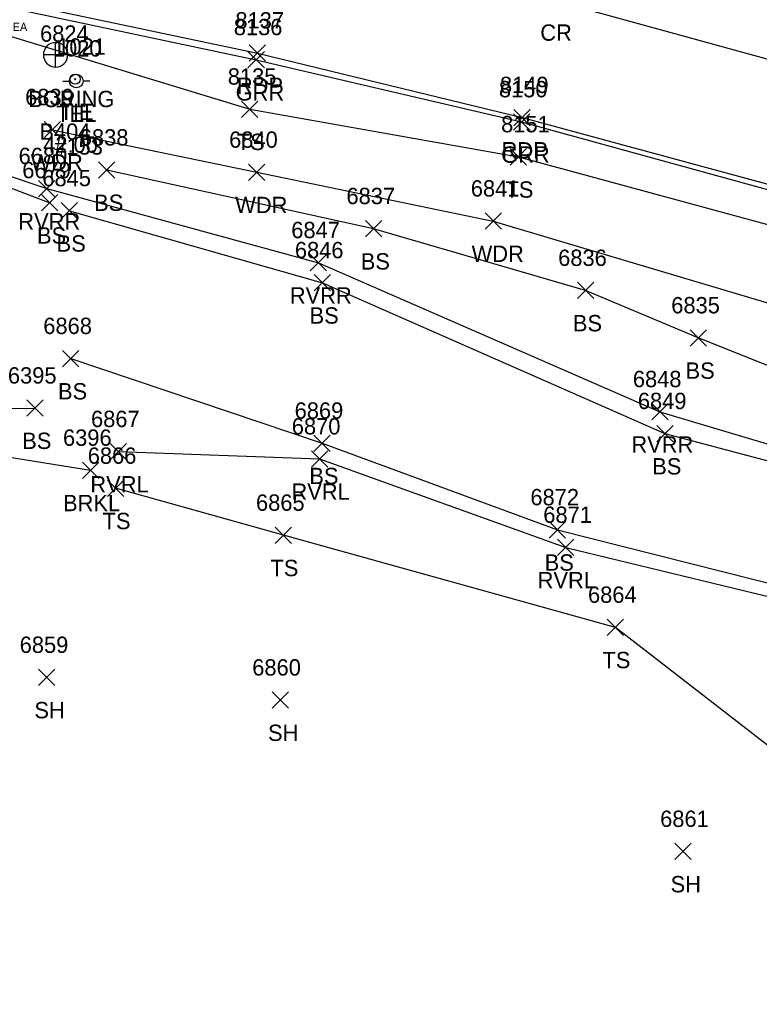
# Model space of a CAD drawing. Extents: x 1588028 to 1589597, y 137576 to 138176.
# Drawn here: x 1588986.3 to 1589076.8, y 137712.9 to 137833.8 of the extents above; entities that cross this region are included whole.
import ezdxf

# ---------------------------------------------------------------- set-up
doc = ezdxf.new("R2010")
doc.units = 0
for name, color, linetype in [('B_C', 7, 'Continuous'), ('C_A', 7, 'Continuous'), ('C_C', 7, 'Continuous'), ('C_I', 7, 'Continuous'), ('CBP', 7, 'Continuous'), ('G_A', 7, 'Continuous'), ('G_C', 7, 'Continuous'), ('G_I', 7, 'Continuous'), ('GA_P', 7, 'Continuous'), ('L_A', 7, 'Continuous'), ('L_I', 7, 'Continuous'), ('L_TIC', 7, 'Continuous'), ('LAWA', 7, 'Continuous'), ('LAWE', 7, 'Continuous'), ('LELB', 7, 'Continuous'), ('P_A', 7, 'Continuous'), ('P_I', 7, 'Continuous'), ('P_TIC', 7, 'Continuous'), ('PET', 7, 'Continuous'), ('PRC', 7, 'Continuous'), ('R_A', 7, 'Continuous'), ('R_I', 7, 'Continuous'), ('R_TIC', 7, 'Continuous'), ('RGR', 7, 'Continuous'), ('U_A', 7, 'Continuous'), ('U_C', 7, 'Continuous'), ('U_I', 7, 'Continuous'), ('UP', 7, 'Continuous')]:
    doc.layers.add(name, color=color, linetype=linetype)

msp = doc.modelspace()

# ---------------------------------------------------------------- linework, layer by layer
at = {"layer": 'CBP'}
for radius in [0.625, 0.0833]:
    msp.add_circle((1588993.08, 137826.57), radius, dxfattribs=at)
at = {"layer": 'GA_P'}
for p, q in [((1588990.69, 137829.55), (1588990.69, 137831.05)), ((1588990.69, 137829.55), (1588989.19, 137829.55)), ((1588992.19, 137829.55), (1588990.69, 137829.55)), ((1588990.69, 137828.05), (1588990.69, 137829.55))]:
    msp.add_line(p, q, dxfattribs=at)
for start, end in [(90, 180), (0, 90), (180, 270), (270, 0)]:
    msp.add_arc((1588990.69, 137829.55), 1.5, start, end, dxfattribs=at)
at = {"layer": 'L_TIC'}
for points in [[(1589013.45, 137821.9), (1589015.45, 137823.9)], [(1589015.45, 137821.9), (1589013.45, 137823.9)], [(1588989.27, 137819.39), (1588991.27, 137821.39)], [(1588991.27, 137819.39), (1588989.27, 137821.39)], [(1589046.33, 137816.07), (1589048.33, 137818.07)], [(1589048.33, 137816.07), (1589046.33, 137818.07)], [(1588995.95, 137814.45), (1588997.95, 137816.45)], [(1588997.95, 137814.45), (1588995.95, 137816.45)], [(1589014.31, 137814.18), (1589016.31, 137816.18)], [(1589016.31, 137814.18), (1589014.31, 137816.18)], [(1588988.6, 137812.18), (1588990.6, 137814.18)], [(1588990.6, 137812.18), (1588988.6, 137814.18)], [(1588988.97, 137810.45), (1588990.97, 137812.45)], [(1588990.97, 137810.45), (1588988.97, 137812.45)], [(1588991.37, 137809.47), (1588993.37, 137811.47)], [(1588993.37, 137809.47), (1588991.37, 137811.47)], [(1589043.24, 137808.21), (1589045.24, 137810.21)], [(1589045.24, 137808.21), (1589043.24, 137810.21)], [(1589028.59, 137807.28), (1589030.59, 137809.28)], [(1589030.59, 137807.28), (1589028.59, 137809.28)], [(1589021.84, 137803.12), (1589023.84, 137805.12)], [(1589023.84, 137803.12), (1589021.84, 137805.12)], [(1589022.33, 137800.66), (1589024.33, 137802.66)], [(1589024.33, 137800.66), (1589022.33, 137802.66)], [(1589054.55, 137799.72), (1589056.55, 137801.72)], [(1589056.55, 137799.72), (1589054.55, 137801.72)], [(1589068.34, 137793.92), (1589070.34, 137795.92)], [(1589070.34, 137793.92), (1589068.34, 137795.92)], [(1588991.54, 137791.39), (1588993.54, 137793.39)], [(1588993.54, 137791.39), (1588991.54, 137793.39)], [(1588987.16, 137785.33), (1588989.16, 137787.33)], [(1588989.16, 137785.33), (1588987.16, 137787.33)], [(1589063.64, 137784.89), (1589065.64, 137786.89)], [(1589065.64, 137784.89), (1589063.64, 137786.89)], [(1589064.26, 137782.21), (1589066.26, 137784.21)], [(1589066.26, 137782.21), (1589064.26, 137784.21)], [(1588997.37, 137780.01), (1588999.37, 137782.01)], [(1588999.37, 137780.01), (1588997.37, 137782.01)], [(1589022.3, 137781.03), (1589024.3, 137783.03)], [(1589024.3, 137781.03), (1589022.3, 137783.03)], [(1589021.99, 137779.11), (1589023.99, 137781.11)], [(1589023.99, 137779.11), (1589021.99, 137781.11)], [(1588993.96, 137777.72), (1588995.96, 137779.72)], [(1588995.96, 137777.72), (1588993.96, 137779.72)], [(1588997.03, 137775.52), (1588999.03, 137777.52)], [(1588999.03, 137775.52), (1588997.03, 137777.52)], [(1589051.1, 137770.44), (1589053.1, 137772.44)], [(1589053.1, 137770.44), (1589051.1, 137772.44)], [(1589017.57, 137769.77), (1589019.57, 137771.77)], [(1589019.57, 137769.77), (1589017.57, 137771.77)], [(1589052.11, 137768.29), (1589054.11, 137770.29)], [(1589054.11, 137768.29), (1589052.11, 137770.29)], [(1589058.2, 137758.51), (1589060.2, 137760.51)], [(1589060.2, 137758.51), (1589058.2, 137760.51)], [(1588988.61, 137752.38), (1588990.61, 137754.38)], [(1588990.61, 137752.38), (1588988.61, 137754.38)], [(1589017.19, 137749.61), (1589019.19, 137751.61)], [(1589019.19, 137749.61), (1589017.19, 137751.61)], [(1589066.46, 137731.09), (1589068.46, 137733.09)], [(1589068.46, 137731.09), (1589066.46, 137733.09)]]:
    msp.add_lwpolyline(points, dxfattribs=at)
at = {"layer": 'LAWA'}
msp.add_lwpolyline([(1588990.27, 137820.39), (1589015.31, 137815.18), (1589044.24, 137809.21), (1589082.76, 137797.73), (1589102.27, 137783.77), (1589136.15, 137768.8), (1589160.7, 137757.03)], dxfattribs=at)
at = {"layer": 'LAWE'}
for points in [[(1588965.44, 137832.87), (1588973.43, 137818.62), (1588989.6, 137813.18), (1589022.84, 137804.12), (1589064.64, 137785.89), (1589085.42, 137779.69), (1589097.72, 137781.17), (1589112.63, 137775.03), (1589131.45, 137759.72), (1589147.93, 137745.25), (1589161.35, 137734.82)], [(1588713.41, 137823.71), (1588738.42, 137825.5), (1588767.27, 137826.98), (1588799.24, 137826.53), (1588827.86, 137827.03), (1588853.9, 137816.5), (1588892.67, 137800.6), (1588920.93, 137790.22), (1588953.81, 137785.34), (1588994.96, 137778.72)], [(1588998.37, 137781.01), (1589022.99, 137780.11), (1589053.11, 137769.29), (1589085.17, 137761.52), (1589118.32, 137748.59), (1589139.23, 137719.4), (1589162.49, 137704.02), (1589194.14, 137678.84), (1589218.55, 137662.87), (1589237.06, 137655.88), (1589274.24, 137640.2), (1589299.98, 137630.61), (1589325.3, 137627.35), (1589364.55, 137614.89), (1589400.15, 137603.63), (1589430.64, 137600.05), (1589464.28, 137596.09), (1589486.71, 137581.4)]]:
    msp.add_lwpolyline(points, dxfattribs=at)
at = {"layer": 'LELB'}
for points in [[(1588976.95, 137800.76), (1588950.62, 137796.9), (1588914.44, 137812.1), (1588887.83, 137826.14), (1588862.59, 137838.68), (1588839.41, 137844.48), (1588814.28, 137844.58), (1588790.42, 137844.54), (1588761.5, 137843.62), (1588744.06, 137845.91), (1588711.1, 137839.15), (1588710.72, 137829.12), (1588738.02, 137826.67), (1588767.07, 137829.2), (1588800.85, 137829.84), (1588826.76, 137827.94), (1588856.44, 137818.62), (1588893.47, 137804.61), (1588923.15, 137792.66), (1588953.98, 137786.08), (1588988.16, 137786.33)], [(1588964.15, 137832.41), (1588972.64, 137818.05), (1588989.97, 137811.45)], [(1588982.15, 137832.74), (1589014.45, 137822.9), (1589047.33, 137817.07), (1589086.55, 137806.43), (1589114.04, 137794.2), (1589138.04, 137783.39), (1589164.04, 137781.22)], [(1589092.95, 137785.5), (1589069.34, 137794.92), (1589055.55, 137800.72), (1589029.59, 137808.28), (1588996.95, 137815.45)], [(1588992.37, 137810.47), (1589023.33, 137801.66), (1589065.26, 137783.21), (1589085.4, 137777.87), (1589097.27, 137780.08), (1589112.23, 137773.55), (1589130.4, 137758.11), (1589147.06, 137743.95), (1589161.02, 137733.26), (1589186.97, 137714.57), (1589213.06, 137701.82), (1589227.47, 137691.94), (1589245.18, 137673.31), (1589268.48, 137660.8), (1589296.93, 137655.07), (1589325.66, 137650.73)], [(1588992.54, 137792.39), (1589023.3, 137782.03), (1589052.1, 137771.44), (1589084.42, 137763.28), (1589121.54, 137752.14), (1589143.04, 137720.61), (1589163.05, 137704.95), (1589194.58, 137680.14), (1589220, 137665.12), (1589237.76, 137657.31), (1589273.63, 137642.37), (1589300.04, 137631.76), (1589324.52, 137628.67), (1589366.23, 137617.74), (1589400.05, 137606.05), (1589430.12, 137603.56), (1589464.26, 137598.64), (1589483.45, 137589.04)], [(1589107.98, 137721.88), (1589082.2, 137741.69), (1589059.2, 137759.51), (1589018.57, 137770.77), (1588998.03, 137776.52)]]:
    msp.add_lwpolyline(points, dxfattribs=at)
at = {"layer": 'P_TIC'}
for points in [[(1589014.38, 137828.77), (1589016.38, 137830.77)], [(1589016.38, 137828.77), (1589014.38, 137830.77)], [(1589046.77, 137820.87), (1589048.77, 137822.87)], [(1589048.77, 137820.87), (1589046.77, 137822.87)]]:
    msp.add_lwpolyline(points, dxfattribs=at)
at = {"layer": 'PET'}
msp.add_lwpolyline([(1588976.42, 137837.98), (1589015.38, 137829.77), (1589047.77, 137821.87), (1589087.62, 137811.07), (1589117.34, 137801.67), (1589165.82, 137785.25), (1589185.23, 137778.17), (1589232.28, 137760.8), (1589265.32, 137747.81), (1589310.31, 137729.83), (1589359.63, 137709.23), (1589389.55, 137696.8), (1589422.31, 137682.69), (1589446.91, 137672.54)], dxfattribs=at)
at = {"layer": 'PRC'}
msp.add_lwpolyline([(1588964.71, 137855.4), (1588980.14, 137852.51), (1589018.19, 137844.35), (1589051.57, 137836.27), (1589092.27, 137825.07), (1589122.68, 137816.23), (1589170.7, 137800.29), (1589190.72, 137793.38), (1589238.44, 137775.62), (1589271.31, 137762.4), (1589315.94, 137744.35), (1589366.22, 137723.58), (1589395.71, 137710.87), (1589428.18, 137697.42), (1589453.33, 137686.42)], dxfattribs=at)
at = {"layer": 'R_TIC'}
for points in [[(1589014.23, 137827.95), (1589016.23, 137829.95)], [(1589016.23, 137827.95), (1589014.23, 137829.95)], [(1589046.72, 137820.35), (1589048.72, 137822.35)], [(1589048.72, 137820.35), (1589046.72, 137822.35)]]:
    msp.add_lwpolyline(points, dxfattribs=at)
at = {"layer": 'RGR'}
msp.add_lwpolyline([(1588981.28, 137836.13), (1589015.23, 137828.95), (1589047.72, 137821.35), (1589087.45, 137810.42), (1589116.48, 137799.61), (1589136.35, 137790.83)], dxfattribs=at)
at = {"layer": 'UP'}
for p, q in [((1588991.55, 137826.33), (1588992.38, 137826.33)), ((1588993.21, 137826.34), (1588993.21, 137826.34)), ((1588994.88, 137826.34), (1588994.05, 137826.34)), ((1588994.05, 137826.34), (1588994.05, 137826.34)), ((1588994.88, 137826.34), (1588994.88, 137826.34))]:
    msp.add_line(p, q, dxfattribs=at)
msp.add_circle((1588993.21, 137826.34), 0.833, dxfattribs=at)

# ---------------------------------------------------------------- texts
at = {"layer": 'B_C'}
msp.add_text('CRACKED   ERODED IN THIS AREA', height=1, dxfattribs=at).set_placement((1588964.7, 137832.47))
at = {"layer": 'C_A'}
msp.add_text('TIE', height=2, dxfattribs=at).set_placement((1588991.16, 137821.57))
at = {"layer": 'C_C'}
msp.add_text('42.00', height=2, dxfattribs=at).set_placement((1588989.17, 137817.57))
at = {"layer": 'C_I'}
msp.add_text('1021', height=2, dxfattribs=at).set_placement((1588990.88, 137829.57))
at = {"layer": 'G_A'}
msp.add_text('BORING', height=2, dxfattribs=at).set_placement((1588987.33, 137823.15))
at = {"layer": 'G_C'}
msp.add_text('B404', height=2, dxfattribs=at).set_placement((1588988.7, 137819.15))
at = {"layer": 'G_I'}
msp.add_text('6824', height=2, dxfattribs=at).set_placement((1588988.78, 137831.15))
at = {"layer": 'L_A'}
for s, p in [('TS', (1589012.86, 137817.9)), ('WDR', (1588987.63, 137815.39)), ('TS', (1589045.74, 137812.07)), ('BS', (1588995.4, 137810.45)), ('WDR', (1589012.67, 137810.18)), ('RVRR', (1588986.12, 137808.18)), ('BS', (1588988.41, 137806.45)), ('BS', (1588990.81, 137805.47)), ('WDR', (1589041.6, 137804.21)), ('BS', (1589028.03, 137803.28)), ('RVRR', (1589019.35, 137799.12)), ('BS', (1589021.77, 137796.66)), ('BS', (1589053.99, 137795.72)), ('BS', (1589067.78, 137789.92)), ('BS', (1588990.98, 137787.39)), ('BS', (1588986.6, 137781.33)), ('RVRR', (1589061.15, 137780.89)), ('BS', (1589063.7, 137778.21)), ('BS', (1589021.74, 137777.03)), ('RVRL', (1588994.94, 137776.01)), ('RVRL', (1589019.55, 137775.11)), ('BRKL', (1588991.6, 137773.72)), ('TS', (1588996.44, 137771.52)), ('TS', (1589016.98, 137765.77)), ('BS', (1589050.54, 137766.44)), ('RVRL', (1589049.68, 137764.29)), ('TS', (1589057.61, 137754.51)), ('SH', (1588988.09, 137748.38)), ('SH', (1589016.68, 137745.61)), ('SH', (1589065.95, 137727.09))]:
    msp.add_text(s, height=2, dxfattribs=at).set_placement(p)
at = {"layer": 'L_I'}
for s, p in [('8135', (1589011.76, 137825.9)), ('6839', (1588986.96, 137823.39)), ('8151', (1589045.21, 137820.07)), ('6838', (1588993.65, 137818.45)), ('6840', (1589011.92, 137818.18)), ('6680', (1588986.16, 137816.18)), ('6679', (1588986.61, 137814.45)), ('6845', (1588989.06, 137813.47)), ('6841', (1589041.5, 137812.21)), ('6837', (1589026.28, 137811.28)), ('6847', (1589019.53, 137807.12)), ('6846', (1589019.97, 137804.66)), ('6836', (1589052.19, 137803.72)), ('6835', (1589066.03, 137797.92)), ('6868', (1588989.18, 137795.39)), ('6395', (1588984.85, 137789.33)), ('6848', (1589061.33, 137788.89)), ('6849', (1589061.94, 137786.21)), ('6869', (1589019.94, 137785.03)), ('6867', (1588995.02, 137784.01)), ('6870', (1589019.59, 137783.11)), ('6396', (1588991.59, 137781.72)), ('6866', (1588994.62, 137779.52)), ('6872', (1589048.79, 137774.44)), ('6865', (1589015.21, 137773.77)), ('6871', (1589050.37, 137772.29)), ('6864', (1589055.84, 137762.51)), ('6859', (1588986.29, 137756.38)), ('6860', (1589014.75, 137753.61)), ('6861', (1589064.67, 137735.09))]:
    msp.add_text(s, height=2, dxfattribs=at).set_placement(p)
at = {"layer": 'P_A'}
for s, p in [('CR', (1589050, 137831.27)), ('RDP', (1589012.87, 137824.77)), ('RDP', (1589045.26, 137816.87))]:
    msp.add_text(s, height=2, dxfattribs=at).set_placement(p)
at = {"layer": 'P_I'}
for s, p in [('8137', (1589012.69, 137832.77)), ('8149', (1589045.07, 137824.87))]:
    msp.add_text(s, height=2, dxfattribs=at).set_placement(p)
at = {"layer": 'R_A'}
for p in [(1589012.72, 137823.95), (1589045.21, 137816.35)]:
    msp.add_text('GRR', height=2, dxfattribs=at).set_placement(p)
at = {"layer": 'R_I'}
for s, p in [('8136', (1589012.49, 137831.95)), ('8150', (1589044.94, 137824.35))]:
    msp.add_text(s, height=2, dxfattribs=at).set_placement(p)
at = {"layer": 'U_A'}
msp.add_text('TEL', height=2, dxfattribs=at).set_placement((1588990.77, 137821.34))
at = {"layer": 'U_C'}
msp.add_text('#153', height=2, dxfattribs=at).set_placement((1588990.52, 137817.34))
at = {"layer": 'U_I'}
msp.add_text('1020', height=2, dxfattribs=at).set_placement((1588990.35, 137829.34))

doc.saveas('drawing.dxf')
